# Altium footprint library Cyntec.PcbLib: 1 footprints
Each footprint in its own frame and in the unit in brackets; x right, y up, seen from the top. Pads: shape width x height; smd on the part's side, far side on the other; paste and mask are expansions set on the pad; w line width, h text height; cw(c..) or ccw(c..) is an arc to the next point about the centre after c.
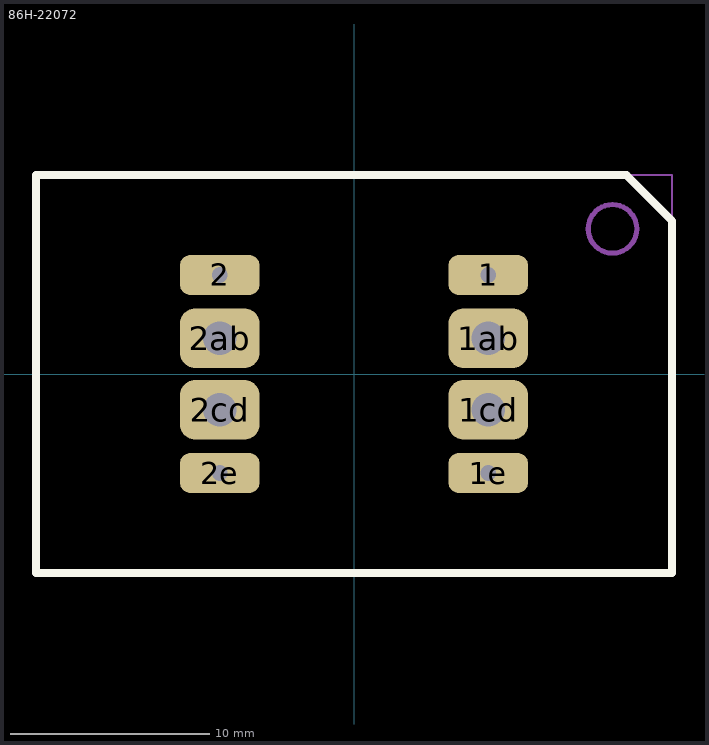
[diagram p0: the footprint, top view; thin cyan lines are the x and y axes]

## 86H-22072 [mm] "1.6kW 386V to 12V"
height 27
pads (8):
  rrect50% 4x2 hole 0.8 square: 1(6.75,4.98) 1e(6.75,-4.98) 2(-6.75,4.98) 2e(-6.75,-4.98)
  rrect50% 4x3 hole 1.7 square: 1ab(6.75,1.8) 1cd(6.75,-1.8) 2ab(-6.75,1.8) 2cd(-6.75,-1.8)
Top Overlay:
  lines w0.4: -16,-10 -16,10 13.7,10 16,7.7 16,-10 -16,-10
M5 Assembly Top:
  circle w0.254: c13,7.3 r1.221
  lines w0.1: -16,-10 -16,10 16,10 16,-10 -16,-10
  text ".Designator" at -1.8,-0.514 h1.02
  text "1" at 12.852,6.852 h0.89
